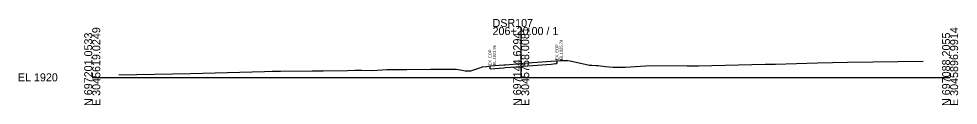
# Model space of a CAD drawing. Extents: x -26 to 19003, y -31 to 24541.
# Drawn here: x 1974.3 to 2302.8, y 9490.3 to 9520.4 of the extents above; entities that cross this region are included whole.
import ezdxf

# ---------------------------------------------------------------- set-up
doc = ezdxf.new("R2010")
doc.units = 0
for name, color, linetype in [('DESIGN - SHEET - Light Grid', 7, 'Continuous'), ('SURVEY - GROUND - Existing Pavement Layer', 7, 'Continuous'), ('SURVEY - GROUND - Existing Pavement Text', 7, 'Continuous'), ('SURVEY - GROUND - Top of Ground', 7, 'Continuous')]:
    doc.layers.add(name, color=color, linetype=linetype)

msp = doc.modelspace()

# ---------------------------------------------------------------- linework, layer by layer
at = {"layer": 'DESIGN - SHEET - Light Grid'}
for p, q in [((2150, 9500), (2150, 9517.55)), ((2000, 9500), (2150, 9500)), ((2150, 9500), (2300, 9500))]:
    msp.add_line(p, q, dxfattribs=at)
at = {"layer": 'SURVEY - GROUND - Existing Pavement Layer'}
for p, q in [((2150.74, 9503.89), (2160.53, 9504.65)), ((2160.53, 9504.65), (2162.12, 9504.78)), ((2162.12, 9504.78), (2162.49, 9504.79)), ((2162.49, 9505.79), (2162.49, 9504.79)), ((2139.11, 9502.96), (2139.11, 9503.96)), ((2139.11, 9502.96), (2143.93, 9503.34)), ((2143.93, 9503.34), (2144.51, 9503.38)), ((2144.51, 9503.38), (2150, 9503.83)), ((2150, 9503.83), (2150.74, 9503.89))]:
    msp.add_line(p, q, dxfattribs=at)
at = {"layer": 'SURVEY - GROUND - Top of Ground'}
msp.add_lwpolyline([(2009.24, 9500.86), (2034.41, 9501.38), (2060.22, 9502.07), (2062.87, 9502.17), (2065.86, 9502.15), (2076.96, 9502.27), (2078.88, 9502.31), (2080.75, 9502.32), (2089.3, 9502.41), (2091.8, 9502.47), (2094.24, 9502.54), (2098.05, 9502.42), (2102.97, 9502.73), (2110.05, 9502.77), (2118.24, 9502.82), (2124.68, 9502.85), (2127.21, 9502.86), (2129.35, 9502.45), (2130.45, 9502.28), (2130.91, 9502.28), (2132.43, 9502.31), (2135.15, 9503.17), (2136.52, 9503.66), (2137.94, 9503.82), (2139.11, 9503.96), (2143.93, 9504.34), (2144.51, 9504.38), (2150, 9504.83), (2150.74, 9504.89), (2160.53, 9505.65), (2162.12, 9505.78), (2162.49, 9505.79), (2163.67, 9505.85), (2166.04, 9505.83), (2166.36, 9505.83), (2167.19, 9505.72), (2173.9, 9504.29), (2174.76, 9504.21), (2176.28, 9504.14), (2176.89, 9504.08), (2179.44, 9503.84), (2182.2, 9503.6), (2185.86, 9503.5), (2186.31, 9503.52), (2195.24, 9504.13), (2208.05, 9503.99), (2210.48, 9503.98), (2212.02, 9504.01), (2235.36, 9504.6), (2238.89, 9504.63), (2253.6, 9505.11), (2264.09, 9505.32), (2290.54, 9505.59)], dxfattribs=at)

# ---------------------------------------------------------------- texts
at = {"layer": 'DESIGN - SHEET - Light Grid'}
for s, p in [('206+20.00 / 1', (2140, 9514.75)), ('DSR107', (2140, 9517.55)), ('EL 1920', (1974, 9498.6))]:
    msp.add_text(s, height=2.8, dxfattribs=at).set_placement(p)
for s, p in [('N 697201.0533', (2000, 9490)), ('E 3045619.0249', (2002.8, 9490)), ('N 697144.6294', (2150, 9490)), ('E 3045758.0081', (2152.8, 9490)), ('N 697088.2055', (2300, 9490)), ('E 3045896.9914', (2302.8, 9490))]:
    msp.add_text(s, height=2.8, rotation=90, dxfattribs=at).set_placement(p)
at = {"layer": 'SURVEY - GROUND - Existing Pavement Text'}
for s, p in [('EX. EOP', (2162.99, 9505.99)), ('EL.1925.79', (2164.49, 9505.99)), ('EX. EOP', (2139.61, 9504.16)), ('EL.1923.96', (2141.11, 9504.16))]:
    msp.add_text(s, height=1, rotation=90, dxfattribs=at).set_placement(p)

doc.saveas('drawing.dxf')
